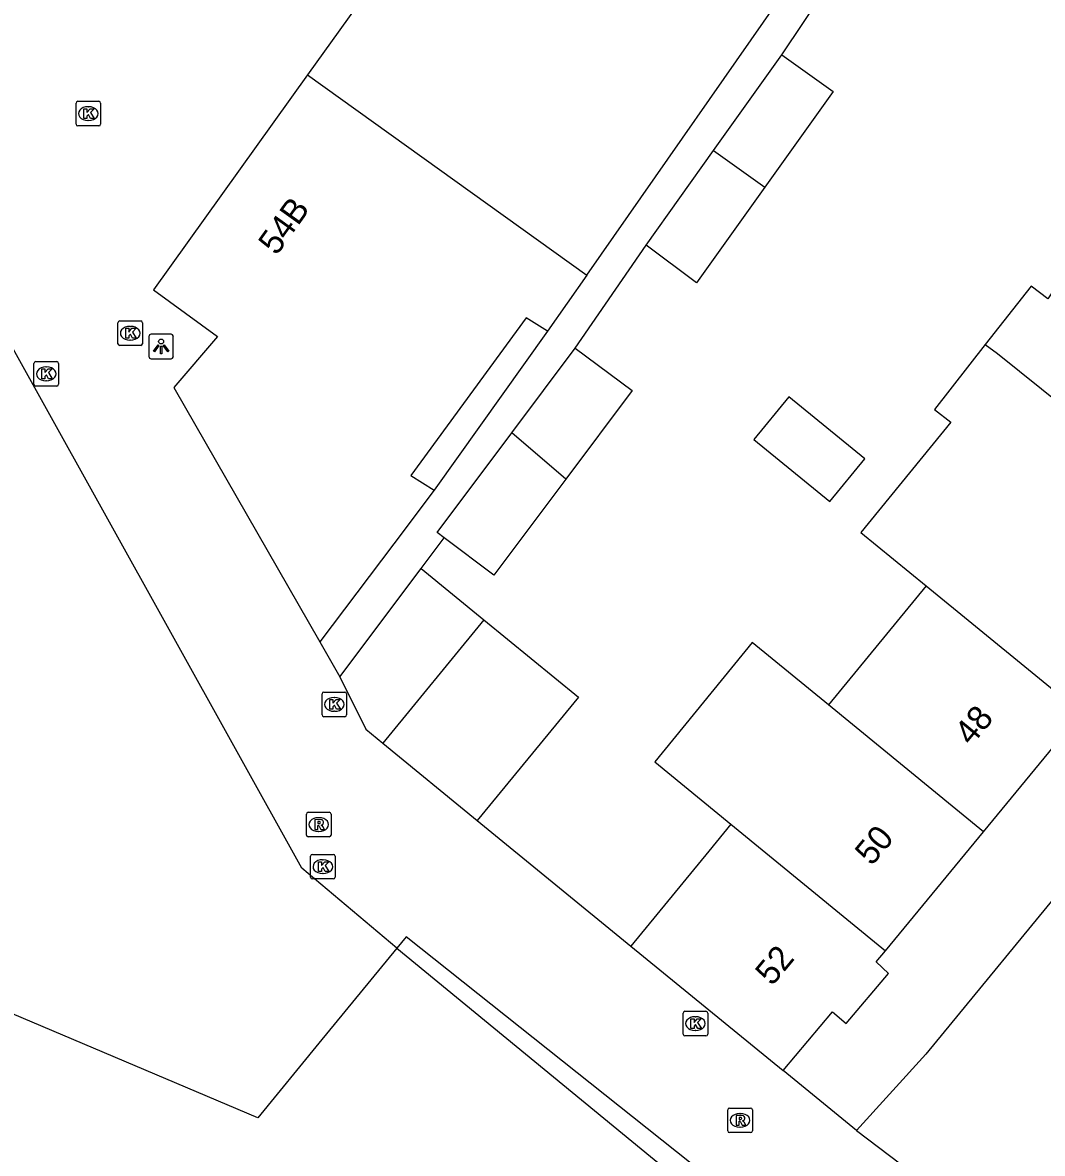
# Model space of a CAD drawing. Extents: x 161771 to 163125, y 382479 to 383177.
# Drawn here: x 162363.81 to 162405.28, y 382599.89 to 382645.91 of the extents above; entities that cross this region are included whole.
import ezdxf

# ---------------------------------------------------------------- set-up
doc = ezdxf.new("R2010")
doc.units = 0
for name, color, linetype in [('IMGEO_Kolk', 7, 'Continuous'), ('IMGEO_Lichtpunt', 7, 'Continuous'), ('IMGEO_Muur', 7, 'Continuous'), ('IMGEO_Pand', 7, 'Continuous'), ('IMGEO_Pand_nummerreeks', 7, 'Continuous'), ('IMGEO_Rijbaan_lokaal_open', 7, 'Continuous'), ('IMGEO_Rioolput', 7, 'Continuous'), ('IMGEO_Voetpad_open', 7, 'Continuous')]:
    doc.layers.add(name, color=color, linetype=linetype)

msp = doc.modelspace()

# ---------------------------------------------------------------- linework, layer by layer
at = {"layer": 'IMGEO_Kolk'}
for p, q in [((162365.982, 382641.782), (162365.982, 382642.634)), ((162366.057, 382642.708), (162366.909, 382642.708)), ((162366.983, 382642.634), (162366.983, 382641.782)), ((162366.47, 382642.488), (162366.495, 382642.488)), ((162366.909, 382641.708), (162366.057, 382641.708)), ((162366.493, 382641.928), (162366.468, 382641.928)), ((162367.685, 382632.844), (162367.685, 382633.696)), ((162367.76, 382633.77), (162368.612, 382633.77)), ((162368.173, 382633.55), (162368.198, 382633.55)), ((162368.686, 382633.696), (162368.686, 382632.844)), ((162368.196, 382632.99), (162368.171, 382632.99)), ((162368.612, 382632.77), (162367.76, 382632.77)), ((162364.271, 382631.192), (162364.271, 382632.044)), ((162364.346, 382632.118), (162365.198, 382632.118)), ((162365.272, 382632.044), (162365.272, 382631.192)), ((162364.759, 382631.898), (162364.784, 382631.898)), ((162365.198, 382631.118), (162364.346, 382631.118)), ((162364.782, 382631.338), (162364.757, 382631.338)), ((162376.062, 382618.666), (162376.914, 382618.666)), ((162375.987, 382617.74), (162375.987, 382618.592)), ((162376.475, 382618.446), (162376.5, 382618.446)), ((162376.988, 382618.592), (162376.988, 382617.74)), ((162376.498, 382617.886), (162376.473, 382617.886)), ((162376.914, 382617.666), (162376.062, 382617.666)), ((162375.521, 382611.137), (162375.521, 382611.989)), ((162375.596, 382612.063), (162376.448, 382612.063)), ((162376.009, 382611.843), (162376.034, 382611.843)), ((162376.522, 382611.989), (162376.522, 382611.137)), ((162376.032, 382611.283), (162376.007, 382611.283)), ((162376.448, 382611.063), (162375.596, 382611.063)), ((162390.672, 382604.749), (162390.672, 382605.601)), ((162390.747, 382605.675), (162391.599, 382605.675)), ((162391.16, 382605.455), (162391.185, 382605.455)), ((162391.673, 382605.601), (162391.673, 382604.749)), ((162391.183, 382604.895), (162391.158, 382604.895)), ((162391.599, 382604.675), (162390.747, 382604.675))]:
    msp.add_line(p, q, dxfattribs=at)
for points in [[(162365.982, 382641.782), (162365.982, 382642.634)], [(162366.057, 382642.708), (162366.909, 382642.708)], [(162366.983, 382642.634), (162366.983, 382641.782)], [(162366.303, 382642.408), (162366.426, 382642.408), (162366.426, 382642.257), (162366.556, 382642.408), (162366.72, 382642.408), (162366.574, 382642.257), (162366.727, 382642.008), (162366.575, 382642.008), (162366.49, 382642.172), (162366.426, 382642.105), (162366.426, 382642.008), (162366.303, 382642.008), (162366.303, 382642.408)], [(162366.909, 382641.708), (162366.057, 382641.708)], [(162367.685, 382632.844), (162367.685, 382633.696)], [(162367.76, 382633.77), (162368.612, 382633.77)], [(162368.006, 382633.47), (162368.129, 382633.47), (162368.129, 382633.319), (162368.259, 382633.47), (162368.423, 382633.47), (162368.277, 382633.319), (162368.43, 382633.07), (162368.278, 382633.07), (162368.193, 382633.234), (162368.129, 382633.167), (162368.129, 382633.07), (162368.006, 382633.07), (162368.006, 382633.47)], [(162368.686, 382633.696), (162368.686, 382632.844)], [(162368.612, 382632.77), (162367.76, 382632.77)], [(162364.271, 382631.192), (162364.271, 382632.044)], [(162364.346, 382632.118), (162365.198, 382632.118)], [(162365.272, 382632.044), (162365.272, 382631.192)], [(162364.592, 382631.818), (162364.715, 382631.818), (162364.715, 382631.667), (162364.845, 382631.818), (162365.009, 382631.818), (162364.863, 382631.667), (162365.016, 382631.418), (162364.864, 382631.418), (162364.779, 382631.582), (162364.715, 382631.515), (162364.715, 382631.418), (162364.592, 382631.418), (162364.592, 382631.818)], [(162365.198, 382631.118), (162364.346, 382631.118)], [(162376.062, 382618.666), (162376.914, 382618.666)], [(162375.987, 382617.74), (162375.987, 382618.592)], [(162376.308, 382618.366), (162376.431, 382618.366), (162376.431, 382618.215), (162376.561, 382618.366), (162376.725, 382618.366), (162376.579, 382618.215), (162376.732, 382617.966), (162376.58, 382617.966), (162376.495, 382618.13), (162376.431, 382618.063), (162376.431, 382617.966), (162376.308, 382617.966), (162376.308, 382618.366)], [(162376.988, 382618.592), (162376.988, 382617.74)], [(162376.914, 382617.666), (162376.062, 382617.666)], [(162375.521, 382611.137), (162375.521, 382611.989)], [(162375.596, 382612.063), (162376.448, 382612.063)], [(162375.842, 382611.763), (162375.965, 382611.763), (162375.965, 382611.612), (162376.095, 382611.763), (162376.259, 382611.763), (162376.113, 382611.612), (162376.266, 382611.363), (162376.114, 382611.363), (162376.029, 382611.527), (162375.965, 382611.46), (162375.965, 382611.363), (162375.842, 382611.363), (162375.842, 382611.763)], [(162376.522, 382611.989), (162376.522, 382611.137)], [(162376.448, 382611.063), (162375.596, 382611.063)], [(162390.672, 382604.749), (162390.672, 382605.601)], [(162390.747, 382605.675), (162391.599, 382605.675)], [(162390.993, 382605.375), (162391.116, 382605.375), (162391.116, 382605.224), (162391.246, 382605.375), (162391.41, 382605.375), (162391.264, 382605.224), (162391.417, 382604.975), (162391.265, 382604.975), (162391.18, 382605.139), (162391.116, 382605.072), (162391.116, 382604.975), (162390.993, 382604.975), (162390.993, 382605.375)], [(162391.673, 382605.601), (162391.673, 382604.749)], [(162391.599, 382604.675), (162390.747, 382604.675)]]:
    msp.add_lwpolyline(points, dxfattribs=at)
for centre, start, end in [((162366.059, 382642.632), 91.552, 178.448), ((162366.059, 382642.632), 91.552, 178.448), ((162366.907, 382642.632), 1.552, 88.448), ((162366.907, 382642.632), 1.552, 88.448), ((162366.059, 382641.784), 181.552, 268.448), ((162366.059, 382641.784), 181.552, 268.448), ((162366.907, 382641.784), 271.552, 358.448), ((162366.907, 382641.784), 271.552, 358.448), ((162367.762, 382633.694), 91.552, 178.448), ((162367.762, 382633.694), 91.552, 178.448), ((162368.61, 382633.694), 1.552, 88.448), ((162368.61, 382633.694), 1.552, 88.448), ((162367.762, 382632.846), 181.552, 268.448), ((162367.762, 382632.846), 181.552, 268.448), ((162368.61, 382632.846), 271.552, 358.448), ((162368.61, 382632.846), 271.552, 358.448), ((162364.348, 382632.042), 91.552, 178.448), ((162364.348, 382632.042), 91.552, 178.448), ((162365.196, 382632.042), 1.552, 88.448), ((162365.196, 382632.042), 1.552, 88.448), ((162364.348, 382631.194), 181.552, 268.448), ((162364.348, 382631.194), 181.552, 268.448), ((162365.196, 382631.194), 271.552, 358.448), ((162365.196, 382631.194), 271.552, 358.448), ((162376.064, 382618.59), 91.552, 178.448), ((162376.064, 382618.59), 91.552, 178.448), ((162376.912, 382618.59), 1.552, 88.448), ((162376.912, 382618.59), 1.552, 88.448), ((162376.064, 382617.742), 181.552, 268.448), ((162376.064, 382617.742), 181.552, 268.448), ((162376.912, 382617.742), 271.552, 358.448), ((162376.912, 382617.742), 271.552, 358.448), ((162375.598, 382611.987), 91.552, 178.448), ((162375.598, 382611.987), 91.552, 178.448), ((162376.446, 382611.987), 1.552, 88.448), ((162376.446, 382611.987), 1.552, 88.448), ((162375.598, 382611.139), 181.552, 268.448), ((162375.598, 382611.139), 181.552, 268.448), ((162376.446, 382611.139), 271.552, 358.448), ((162376.446, 382611.139), 271.552, 358.448), ((162390.749, 382605.599), 91.552, 178.448), ((162390.749, 382605.599), 91.552, 178.448), ((162391.597, 382605.599), 1.552, 88.448), ((162391.597, 382605.599), 1.552, 88.448), ((162390.749, 382604.751), 181.552, 268.448), ((162390.749, 382604.751), 181.552, 268.448), ((162391.597, 382604.751), 271.552, 358.448), ((162391.597, 382604.751), 271.552, 358.448)]:
    msp.add_arc(centre, 0.0765, start, end, dxfattribs=at)
for centre, major_axis, ratio, start_param, end_param in [((162366.469, 382642.208), (-0.387, 0.002), 0.722429, 4.712389, 7.853982), ((162366.494, 382642.208), (-0.39, 0.002), 0.717154, 1.570796, 4.712389), ((162368.172, 382633.27), (-0.387, 0.002), 0.722429, 4.712389, 7.853982), ((162368.197, 382633.27), (-0.39, 0.002), 0.717154, 1.570796, 4.712389), ((162364.758, 382631.618), (-0.387, 0.002), 0.722429, 4.712389, 7.853982), ((162364.783, 382631.618), (-0.39, 0.002), 0.717154, 1.570796, 4.712389), ((162376.474, 382618.166), (-0.387, 0.002), 0.722429, 4.712389, 7.853982), ((162376.499, 382618.166), (-0.39, 0.002), 0.717154, 1.570796, 4.712389), ((162376.008, 382611.563), (-0.387, 0.002), 0.722429, 4.712389, 7.853982), ((162376.033, 382611.563), (-0.39, 0.002), 0.717154, 1.570796, 4.712389), ((162391.159, 382605.175), (-0.387, 0.002), 0.722429, 4.712389, 7.853982), ((162391.184, 382605.175), (-0.39, 0.002), 0.717154, 1.570796, 4.712389)]:
    msp.add_ellipse(centre, major_axis=major_axis, ratio=ratio, start_param=start_param, end_param=end_param, dxfattribs=at)
at = {"layer": 'IMGEO_Lichtpunt'}
for p, q in [((162368.944, 382633.134), (162368.944, 382632.327)), ((162368.944, 382633.134), (162368.944, 382632.327)), ((162369.846, 382633.229), (162369.038, 382633.229)), ((162369.846, 382633.229), (162369.038, 382633.229)), ((162369.94, 382632.327), (162369.94, 382633.134)), ((162369.94, 382632.327), (162369.94, 382633.134)), ((162369.038, 382632.233), (162369.846, 382632.233)), ((162369.038, 382632.233), (162369.846, 382632.233))]:
    msp.add_line(p, q, dxfattribs=at)
for points in [[(162369.318, 382632.798), (162369.357, 382632.77), (162369.169, 382632.508), (162369.131, 382632.535), (162369.318, 382632.798)], [(162369.42, 382632.75), (162369.467, 382632.75), (162369.467, 382632.428), (162369.42, 382632.428), (162369.42, 382632.75)], [(162369.53, 382632.77), (162369.568, 382632.797), (162369.755, 382632.535), (162369.716, 382632.507), (162369.53, 382632.77)]]:
    msp.add_lwpolyline(points, dxfattribs=at)
msp.add_circle((162369.443, 382632.932), 0.0994, dxfattribs=at)
for centre, start, end in [((162369.038, 382633.134), 90, 180), ((162369.038, 382633.134), 90, 180), ((162369.846, 382633.134), 0, 90), ((162369.846, 382633.134), 0, 90), ((162369.038, 382632.327), 180, 270), ((162369.038, 382632.327), 180, 270), ((162369.846, 382632.327), 270, 0), ((162369.846, 382632.327), 270, 360)]:
    msp.add_arc(centre, 0.0946, start, end, dxfattribs=at)
at = {"layer": 'IMGEO_Muur'}
msp.add_lwpolyline([(162382.303, 382613.442), (162388.547, 382608.33)], dxfattribs=at)
at = {"layer": 'IMGEO_Pand'}
for points in [[(162383.916, 382655.658), (162375.4, 382643.786)], [(162386.758, 382635.639), (162395.631, 382648.374)], [(162391.913, 382640.704), (162394.693, 382644.6)], [(162394.693, 382644.6), (162396.781, 382643.109), (162394.002, 382639.214)], [(162375.4, 382643.786), (162369.127, 382635.04), (162371.743, 382633.137), (162369.966, 382631.066), (162375.897, 382620.708)], [(162375.4, 382643.786), (162386.758, 382635.639)], [(162389.168, 382636.856), (162391.913, 382640.704)], [(162391.913, 382640.704), (162394.002, 382639.214)], [(162409.839, 382638.691), (162408.719, 382639.447), (162405.499, 382634.676), (162404.822, 382635.183), (162402.963, 382632.807)], [(162394.002, 382639.214), (162391.223, 382635.318), (162389.168, 382636.856)], [(162386.758, 382635.639), (162385.162, 382633.349)], [(162385.162, 382633.349), (162384.286, 382633.894), (162379.594, 382627.484), (162380.551, 382626.89)], [(162383.704, 382629.221), (162386.283, 382632.669)], [(162386.283, 382632.669), (162388.6, 382630.935), (162385.903, 382627.33)], [(162402.963, 382632.807), (162400.9, 382630.171), (162401.566, 382629.645), (162397.899, 382625.166), (162400.552, 382622.994)], [(162402.963, 382632.807), (162403.454, 382632.444), (162407.997, 382628.803)], [(162396.638, 382626.422), (162398.059, 382628.159), (162394.969, 382630.688), (162393.548, 382628.952), (162396.638, 382626.422)], [(162380.952, 382624.94), (162380.664, 382625.156), (162383.704, 382629.221)], [(162385.903, 382627.33), (162383.704, 382629.221)], [(162385.903, 382627.33), (162382.981, 382623.423), (162380.952, 382624.94)], [(162380.551, 382626.89), (162378.905, 382624.703), (162375.897, 382620.708)], [(162376.707, 382619.293), (162380.021, 382623.695)], [(162380.021, 382623.695), (162382.566, 382621.611)], [(162400.552, 382622.994), (162396.582, 382618.144)], [(162400.552, 382622.994), (162406.871, 382617.818)], [(162379.028, 382608.247), (162375.863, 382604.377), (162373.376, 382601.335), (162322.929, 382622.738)], [(162382.566, 382621.611), (162378.464, 382616.586)], [(162382.566, 382621.611), (162386.413, 382618.462), (162382.303, 382613.442)], [(162396.582, 382618.144), (162393.487, 382620.679), (162389.517, 382615.828), (162392.611, 382613.294)], [(162376.707, 382619.293), (162377.769, 382617.155), (162378.464, 382616.586)], [(162402.886, 382612.981), (162396.582, 382618.144)], [(162402.886, 382612.981), (162406.871, 382617.818)], [(162378.464, 382616.586), (162382.303, 382613.442)], [(162392.611, 382613.294), (162391.715, 382612.199), (162388.547, 382608.33)], [(162392.611, 382613.294), (162398.9, 382608.143)], [(162398.9, 382608.143), (162402.886, 382612.981)], [(162379.028, 382608.247), (162391.016, 382598.4)], [(162388.547, 382608.33), (162394.737, 382603.262)], [(162394.737, 382603.262), (162396.744, 382605.652), (162397.302, 382605.178), (162399.022, 382607.215), (162398.524, 382607.687), (162398.9, 382608.143)]]:
    msp.add_lwpolyline(points, dxfattribs=at)
at = {"layer": 'IMGEO_Rijbaan_lokaal_open'}
for points in [[(162379.028, 382608.247), (162375.169, 382611.496), (162356.474, 382645.131), (162355.836, 382644.864)], [(162375.897, 382620.708), (162376.707, 382619.293)], [(162382.303, 382613.442), (162388.547, 382608.33)], [(162391.524, 382599.061), (162379.408, 382608.712), (162379.028, 382608.247)], [(162397.717, 382600.824), (162394.737, 382603.262)], [(162397.717, 382600.824), (162401.803, 382597.737), (162402.538, 382596.903)]]:
    msp.add_lwpolyline(points, dxfattribs=at)
at = {"layer": 'IMGEO_Rioolput'}
for p, q in [((162375.353, 382612.85), (162375.353, 382613.702)), ((162375.428, 382613.776), (162376.28, 382613.776)), ((162376.354, 382613.702), (162376.354, 382612.85)), ((162375.841, 382613.556), (162375.866, 382613.556)), ((162376.28, 382612.776), (162375.428, 382612.776)), ((162375.864, 382612.996), (162375.839, 382612.996)), ((162392.488, 382600.813), (162392.488, 382601.665)), ((162392.563, 382601.739), (162393.415, 382601.739)), ((162393.489, 382601.665), (162393.489, 382600.813)), ((162392.976, 382601.519), (162393.001, 382601.519)), ((162393.415, 382600.739), (162392.563, 382600.739)), ((162392.999, 382600.959), (162392.974, 382600.959))]:
    msp.add_line(p, q, dxfattribs=at)
for points in [[(162375.353, 382612.85), (162375.353, 382613.702)], [(162375.428, 382613.776), (162376.28, 382613.776)], [(162376.354, 382613.702), (162376.354, 382612.85)], [(162375.942, 382613.474), (162375.69, 382613.476), (162375.69, 382613.076)], [(162375.69, 382613.076), (162375.814, 382613.076), (162375.814, 382613.238), (162375.825, 382613.238)], [(162375.868, 382613.395), (162375.814, 382613.395), (162375.814, 382613.314)], [(162375.814, 382613.314), (162375.866, 382613.314)], [(162375.872, 382613.209), (162375.943, 382613.076), (162376.083, 382613.076), (162376.018, 382613.202)], [(162376.28, 382612.776), (162375.428, 382612.776)], [(162392.488, 382600.813), (162392.488, 382601.665)], [(162392.563, 382601.739), (162393.415, 382601.739)], [(162393.489, 382601.665), (162393.489, 382600.813)], [(162393.077, 382601.437), (162392.825, 382601.439), (162392.825, 382601.039)], [(162392.825, 382601.039), (162392.949, 382601.039), (162392.949, 382601.201), (162392.96, 382601.201)], [(162393.003, 382601.358), (162392.949, 382601.358), (162392.949, 382601.277)], [(162392.949, 382601.277), (162393.001, 382601.277)], [(162393.007, 382601.172), (162393.078, 382601.039), (162393.218, 382601.039), (162393.153, 382601.165)], [(162393.415, 382600.739), (162392.563, 382600.739)]]:
    msp.add_lwpolyline(points, dxfattribs=at)
for centre, radius, start, end in [((162375.43, 382613.7), 0.0765, 91.552, 178.448), ((162375.43, 382613.7), 0.0765, 91.552, 178.448), ((162376.278, 382613.7), 0.0765, 1.552, 88.448), ((162376.278, 382613.7), 0.0765, 1.552, 88.448), ((162375.824, 382613.185), 0.0533, 26.0293, 88.6989), ((162375.85, 382613.503), 0.19, 274.7715, 282.9687), ((162375.874, 382613.299), 0.0964, 77.0061, 93.1865), ((162375.888, 382613.356), 0.0378, 276.6634, 79.6772), ((162375.941, 382613.364), 0.109, 350.3612, 89.416), ((162375.939, 382613.364), 0.112, 277.5842, 350.9817), ((162375.923, 382613.149), 0.108, 29.5134, 73.7905), ((162375.43, 382612.852), 0.0765, 181.552, 268.448), ((162375.43, 382612.852), 0.0765, 181.552, 268.448), ((162376.278, 382612.852), 0.0765, 271.552, 358.448), ((162376.278, 382612.852), 0.0765, 271.552, 358.448), ((162392.565, 382601.663), 0.0765, 91.552, 178.448), ((162392.565, 382601.663), 0.0765, 91.552, 178.448), ((162393.413, 382601.663), 0.0765, 1.552, 88.448), ((162393.413, 382601.663), 0.0765, 1.552, 88.448), ((162392.959, 382601.148), 0.0533, 26.0293, 88.6989), ((162392.985, 382601.466), 0.19, 274.7715, 282.9687), ((162393.009, 382601.262), 0.0964, 77.0061, 93.1865), ((162393.023, 382601.319), 0.0378, 276.6634, 79.6772), ((162393.076, 382601.327), 0.109, 350.3612, 89.416), ((162393.074, 382601.327), 0.112, 277.5842, 350.9817), ((162393.058, 382601.112), 0.108, 29.5134, 73.7905), ((162392.565, 382600.815), 0.0765, 181.552, 268.448), ((162392.565, 382600.815), 0.0765, 181.552, 268.448), ((162393.413, 382600.815), 0.0765, 271.552, 358.448), ((162393.413, 382600.815), 0.0765, 271.552, 358.448)]:
    msp.add_arc(centre, radius, start, end, dxfattribs=at)
for centre, major_axis, ratio, start_param, end_param in [((162375.84, 382613.276), (-0.387, 0.002), 0.722429, 4.712389, 7.853982), ((162375.865, 382613.276), (-0.39, 0.002), 0.717154, 1.570796, 4.712389), ((162392.975, 382601.239), (-0.387, 0.002), 0.722429, 4.712389, 7.853982), ((162393, 382601.239), (-0.39, 0.002), 0.717154, 1.570796, 4.712389)]:
    msp.add_ellipse(centre, major_axis=major_axis, ratio=ratio, start_param=start_param, end_param=end_param, dxfattribs=at)
at = {"layer": 'IMGEO_Voetpad_open'}
for points in [[(162481.155, 382756.282), (162479.277, 382750), (162475.552, 382737.539), (162469.715, 382720.652), (162462.007, 382700.842), (162457.539, 382690.752), (162451.64, 382678.977), (162443.703, 382664.454), (162438.387, 382655.596), (162432.385, 382646.085), (162421.193, 382630.033), (162412.885, 382618.959), (162400.55, 382603.937), (162397.717, 382600.824)], [(162394.693, 382644.6), (162400.026, 382652.594), (162419.717, 382683.993)], [(162386.283, 382632.669), (162389.168, 382636.856)], [(162385.162, 382633.349), (162380.551, 382626.89)], [(162380.021, 382623.695), (162380.952, 382624.94)]]:
    msp.add_lwpolyline(points, dxfattribs=at)

# ---------------------------------------------------------------- texts
at = {"layer": 'IMGEO_Pand_nummerreeks'}
for s, rotation, p in [('54B', 54.3503, (162374.138, 382636.399)), ('48', 50.3306, (162402.393, 382616.442)), ('50', 50.3306, (162398.345, 382611.56)), ('52', 50.3306, (162394.293, 382606.673))]:
    msp.add_text(s, height=1, rotation=rotation, dxfattribs=at).set_placement(p)

doc.saveas('drawing.dxf')
